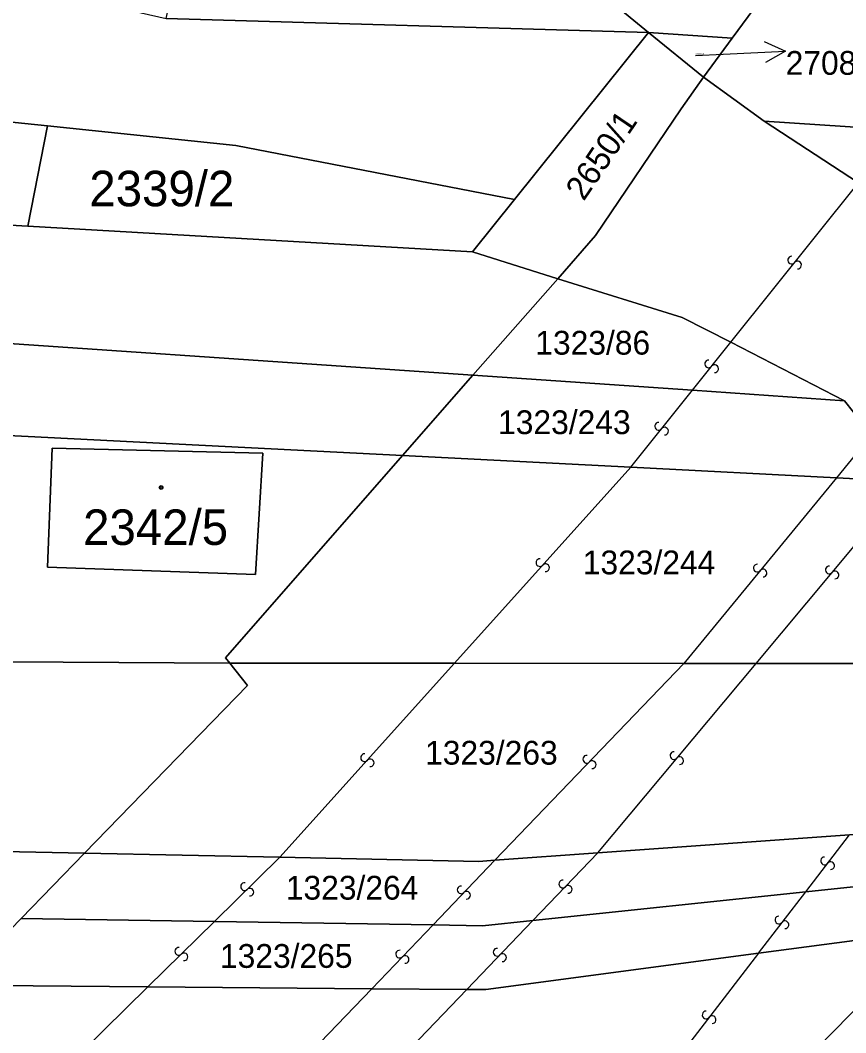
# Model space of a CAD drawing. Extents: x -596024 to -594475, y -1163820 to -1161957.
# Drawn here: x -595780.97 to -595741.38, y -1163112.33 to -1163063.81 of the extents above; entities that cross this region are included whole.
import ezdxf

# ---------------------------------------------------------------- set-up
doc = ezdxf.new("R2010")
doc.units = 0
for name, color, linetype in [('Level 1', 7, 'Continuous'), ('Level 13', 7, 'Continuous'), ('Level 3', 7, 'Continuous'), ('Level 4', 7, 'Continuous'), ('Level 5', 7, 'Continuous'), ('Level 57', 7, 'Continuous'), ('Level 60', 7, 'Continuous')]:
    doc.layers.add(name, color=color, linetype=linetype)

msp = doc.modelspace()

# ---------------------------------------------------------------- linework, layer by layer
at = {"layer": 'Level 1'}
for points in [[(-595779.65, -1163068.86), (-595798.9, -1163066.88), (-595824.16, -1163062.75), (-595839.42, -1163058.15)], [(-595756.75, -1163059.54), (-595750.84, -1163064.39)], [(-595746.83, -1163064.67), (-595743.48, -1163060.13)], [(-595773.96, -1163063.72), (-595750.84, -1163064.39)], [(-595750.84, -1163064.39), (-595757.26, -1163072.39)], [(-595750.84, -1163064.39), (-595746.83, -1163064.67)], [(-595750.84, -1163064.39), (-595748.2, -1163066.53)], [(-595748.2, -1163066.53), (-595746.83, -1163064.67)], [(-595755.19, -1163076.19), (-595753.38, -1163074.12), (-595749.27, -1163068.05), (-595748.2, -1163066.53)], [(-595748.2, -1163066.53), (-595745.29, -1163068.64)], [(-595780.6, -1163073.68), (-595779.65, -1163068.86)], [(-595779.65, -1163068.86), (-595770.62, -1163069.8), (-595757.26, -1163072.39)], [(-595745.29, -1163068.64), (-595740.77, -1163071.6)], [(-595745.29, -1163068.64), (-595738.74, -1163069.07)], [(-595780.6, -1163073.68), (-595817.56, -1163071.57), (-595822.9, -1163070.28)], [(-595759.28, -1163074.91), (-595757.26, -1163072.39)], [(-595780.6, -1163073.68), (-595759.28, -1163074.91)], [(-595759.26, -1163080.82), (-595817.3, -1163076.86), (-595823.71, -1163075.27)], [(-595759.28, -1163074.91), (-595755.19, -1163076.19)], [(-595755.19, -1163076.19), (-595759.26, -1163080.82)], [(-595755.19, -1163076.19), (-595749.22, -1163078.05), (-595746.89, -1163079.24)], [(-595741.44, -1163082.04), (-595746.89, -1163079.24)], [(-595762.63, -1163084.67), (-595816.82, -1163081.91), (-595824.57, -1163080.54)], [(-595759.26, -1163080.82), (-595762.63, -1163084.67)], [(-595759.26, -1163080.82), (-595748.73, -1163081.54)], [(-595748.73, -1163081.54), (-595741.44, -1163082.04)], [(-595740.15, -1163083.68), (-595741.44, -1163082.04)], [(-595779.44, -1163084.32), (-595769.33, -1163084.56), (-595769.69, -1163090.36), (-595779.66, -1163090.01), (-595779.44, -1163084.32)], [(-595762.63, -1163084.67), (-595771.12, -1163094.36), (-595770.92, -1163094.61)], [(-595762.63, -1163084.67), (-595751.68, -1163085.23)], [(-595751.68, -1163085.23), (-595741.83, -1163085.73)], [(-595741.83, -1163085.73), (-595738.38, -1163085.91)], [(-595770.92, -1163094.61), (-595794.91, -1163094.47)], [(-595777.88, -1163103.73), (-595770.07, -1163095.69), (-595770.92, -1163094.61)], [(-595760.14, -1163094.62), (-595770.92, -1163094.61)], [(-595749.14, -1163094.63), (-595760.14, -1163094.62)], [(-595745.68, -1163094.63), (-595749.14, -1163094.63)], [(-595734.88, -1163094.64), (-595745.68, -1163094.63)], [(-595777.88, -1163103.73), (-595815.28, -1163102.95), (-595831.2, -1163101.51)], [(-595753.27, -1163103.71), (-595741.2, -1163102.85)], [(-595780.92, -1163106.86), (-595777.88, -1163103.73)], [(-595777.88, -1163103.73), (-595768.51, -1163103.92)], [(-595768.51, -1163103.92), (-595758.98, -1163104.12), (-595758.2, -1163104.06)], [(-595758.2, -1163104.06), (-595753.27, -1163103.71)], [(-595734.51, -1163104.65), (-595743.3, -1163105.57)], [(-595743.3, -1163105.57), (-595756.38, -1163106.95)], [(-595784.03, -1163110.05), (-595780.92, -1163106.86)], [(-595780.92, -1163106.86), (-595771.65, -1163107)], [(-595771.65, -1163107), (-595761.17, -1163107.16)], [(-595761.17, -1163107.16), (-595758.79, -1163107.2), (-595756.38, -1163106.95)], [(-595745.57, -1163108.52), (-595737.21, -1163107.41)], [(-595745.15, -1163115.51), (-595737.21, -1163107.41)], [(-595745.57, -1163108.52), (-595758.64, -1163110.26), (-595759.55, -1163110.25)], [(-595784.03, -1163110.05), (-595774.84, -1163110.13)], [(-595774.84, -1163110.13), (-595764.11, -1163110.22)], [(-595764.11, -1163110.22), (-595759.55, -1163110.25)]]:
    msp.add_lwpolyline(points, dxfattribs=at)
at = {"layer": 'Level 13'}
for centre, start, end in [((-595743.973, -1163075.303), 88.6764, 320.7744), ((-595743.687, -1163075.536), 268.4619, 141.0519), ((-595747.953, -1163080.273), 88.7129, 320.8109), ((-595747.667, -1163080.506), 268.4985, 141.0885), ((-595750.353, -1163083.264), 88.7319, 320.8299), ((-595750.067, -1163083.496), 268.5174, 141.1074), ((-595756.046, -1163089.795), 85.3552, 317.4532), ((-595755.774, -1163090.044), 265.1407, 137.7307), ((-595745.622, -1163090.063), 87.7604, 320.3504), ((-595745.339, -1163090.298), 267.9748, 140.0728), ((-595742.17, -1163090.15), 87.4381, 319.5361), ((-595741.889, -1163090.389), 267.2237, 139.8137), ((-595764.456, -1163099.145), 85.3855, 317.4835), ((-595753.802, -1163099.222), 83.3047, 315.8947), ((-595749.62, -1163099.05), 87.4804, 319.5784), ((-595749.339, -1163099.289), 267.2659, 139.8559), ((-595764.184, -1163099.394), 265.1711, 137.7611), ((-595753.538, -1163099.479), 263.5191, 135.6171), ((-595742.395, -1163104.096), 89.7025, 321.8005), ((-595742.105, -1163104.323), 269.488, 142.078), ((-595770.208, -1163105.327), 81.8201, 313.9181), ((-595769.952, -1163105.592), 261.6056, 134.1956), ((-595759.822, -1163105.482), 83.3852, 315.9752), ((-595754.952, -1163105.201), 83.5456, 315.6436), ((-595754.688, -1163105.458), 263.3311, 135.9211), ((-595759.558, -1163105.739), 263.5996, 135.6976), ((-595744.585, -1163106.926), 89.7948, 321.8928), ((-595744.295, -1163107.153), 269.5803, 142.1703), ((-595773.368, -1163108.427), 81.8288, 313.9268), ((-595758.102, -1163108.471), 83.5238, 315.6218), ((-595773.112, -1163108.692), 261.6143, 134.2043), ((-595762.772, -1163108.562), 83.304, 315.894), ((-595762.508, -1163108.819), 263.5185, 135.6165), ((-595757.838, -1163108.728), 263.3094, 135.8994), ((-595748.075, -1163111.477), 89.6077, 322.1977), ((-595747.785, -1163111.704), 269.8222, 141.9202)]:
    msp.add_arc(centre, 0.184, start, end, dxfattribs=at)
at = {"layer": 'Level 3'}
for points in [[(-595746.89, -1163079.24), (-595740.77, -1163071.6)], [(-595748.73, -1163081.54), (-595746.89, -1163079.24)], [(-595751.68, -1163085.23), (-595748.73, -1163081.54)], [(-595740.15, -1163083.68), (-595741.83, -1163085.73)], [(-595760.14, -1163094.62), (-595751.68, -1163085.23)], [(-595741.83, -1163085.73), (-595749.14, -1163094.63)], [(-595745.68, -1163094.63), (-595738.38, -1163085.91)], [(-595768.51, -1163103.92), (-595760.14, -1163094.62)], [(-595749.14, -1163094.63), (-595758.2, -1163104.06)], [(-595753.27, -1163103.71), (-595745.68, -1163094.63)], [(-595743.3, -1163105.57), (-595741.2, -1163102.85)], [(-595771.65, -1163107), (-595768.51, -1163103.92)], [(-595756.38, -1163106.95), (-595753.27, -1163103.71)], [(-595758.2, -1163104.06), (-595761.17, -1163107.16)], [(-595745.57, -1163108.52), (-595743.3, -1163105.57)], [(-595774.84, -1163110.13), (-595771.65, -1163107)], [(-595761.17, -1163107.16), (-595764.11, -1163110.22)], [(-595759.55, -1163110.25), (-595756.38, -1163106.95)], [(-595745.57, -1163108.52), (-595750.29, -1163114.66), (-595752.01, -1163116.21)], [(-595782.22, -1163117.37), (-595774.84, -1163110.13)], [(-595764.11, -1163110.22), (-595770.72, -1163117.1)], [(-595766.01, -1163116.99), (-595759.55, -1163110.25)]]:
    msp.add_lwpolyline(points, dxfattribs=at)
at = {"layer": 'Level 5'}
for radius in [0.09, 0.0521]:
    msp.add_circle((-595774.21, -1163086.2), radius, dxfattribs=at)
at = {"layer": 'Level 57'}
for p, q in [((-595748.59, -1163065.49), (-595747.256, -1163065.425)), ((-595747.256, -1163065.425), (-595744.26, -1163065.28))]:
    msp.add_line(p, q, dxfattribs=at)
msp.add_lwpolyline([(-595745.283, -1163064.829), (-595744.26, -1163065.28), (-595745.234, -1163065.828)], dxfattribs=at)
at = {"layer": 'Level 60'}
for points in [[(-595756.75, -1163059.54), (-595750.84, -1163064.39), (-595773.96, -1163063.72), (-595770.91, -1163049.99), (-595770.04, -1163046.08), (-595769.44, -1163043.38), (-595767.99, -1163036.88), (-595764.76, -1163037.03), (-595765.33, -1163056.47), (-595758.86, -1163056.82)], [(-595841.12, -1163065.86), (-595839.42, -1163058.15), (-595824.16, -1163062.75), (-595798.9, -1163066.88), (-595779.65, -1163068.86), (-595780.6, -1163073.68), (-595817.56, -1163071.57), (-595822.9, -1163070.28)], [(-595750.84, -1163064.39), (-595756.75, -1163059.54), (-595743.48, -1163060.13), (-595746.83, -1163064.67)], [(-595755.19, -1163076.19), (-595759.28, -1163074.91), (-595757.26, -1163072.39), (-595750.84, -1163064.39), (-595748.2, -1163066.53), (-595749.27, -1163068.05), (-595753.38, -1163074.12)], [(-595748.2, -1163066.53), (-595750.84, -1163064.39), (-595746.83, -1163064.67)], [(-595748.2, -1163066.53), (-595745.29, -1163068.64), (-595740.77, -1163071.6), (-595739.53, -1163072.41), (-595735, -1163077.41), (-595733.49, -1163079.07), (-595733.06, -1163079.55), (-595730.7, -1163082.19), (-595727.93, -1163085.61), (-595723.18, -1163091.87), (-595722.83, -1163092.35), (-595727.94, -1163097.89), (-595730.64, -1163094.64), (-595732.87, -1163092.03), (-595735.07, -1163089.45), (-595738.38, -1163085.91), (-595740.15, -1163083.68), (-595741.44, -1163082.04), (-595746.89, -1163079.24), (-595749.22, -1163078.05), (-595755.19, -1163076.19), (-595753.38, -1163074.12), (-595749.27, -1163068.05)], [(-595779.65, -1163068.86), (-595770.62, -1163069.8), (-595757.26, -1163072.39), (-595759.28, -1163074.91), (-595780.6, -1163073.68)], [(-595703.87, -1163071.37), (-595706.69, -1163074.49), (-595718.57, -1163073.74), (-595727.72, -1163073.16), (-595731.39, -1163072.93), (-595739.53, -1163072.41), (-595740.77, -1163071.6), (-595745.29, -1163068.64), (-595738.74, -1163069.07), (-595728.81, -1163069.72), (-595725.06, -1163069.97), (-595716.06, -1163070.56)], [(-595759.26, -1163080.82), (-595817.3, -1163076.86), (-595823.71, -1163075.27), (-595822.9, -1163070.28), (-595817.56, -1163071.57), (-595780.6, -1163073.68), (-595759.28, -1163074.91), (-595755.19, -1163076.19)], [(-595762.63, -1163084.67), (-595816.82, -1163081.91), (-595824.57, -1163080.54), (-595823.71, -1163075.27), (-595817.3, -1163076.86), (-595759.26, -1163080.82)], [(-595759.26, -1163080.82), (-595755.19, -1163076.19), (-595749.22, -1163078.05), (-595746.89, -1163079.24), (-595741.44, -1163082.04), (-595748.73, -1163081.54)], [(-595762.63, -1163084.67), (-595759.26, -1163080.82), (-595748.73, -1163081.54), (-595741.44, -1163082.04), (-595740.15, -1163083.68), (-595738.38, -1163085.91), (-595741.83, -1163085.73), (-595751.68, -1163085.23)], [(-595769.33, -1163084.56), (-595779.44, -1163084.32), (-595779.66, -1163090.01), (-595769.69, -1163090.36)], [(-595779.44, -1163084.32), (-595769.33, -1163084.56), (-595769.69, -1163090.36), (-595779.66, -1163090.01)], [(-595771.12, -1163094.36), (-595762.63, -1163084.67), (-595751.68, -1163085.23), (-595741.83, -1163085.73), (-595738.38, -1163085.91), (-595735.07, -1163089.45), (-595732.87, -1163092.03), (-595730.64, -1163094.64), (-595734.88, -1163094.64), (-595745.68, -1163094.63), (-595749.14, -1163094.63), (-595760.14, -1163094.62), (-595770.92, -1163094.61)], [(-595770.07, -1163095.69), (-595777.88, -1163103.73), (-595815.28, -1163102.95), (-595831.2, -1163101.51), (-595830.15, -1163092.76), (-595815.73, -1163094.58), (-595808.11, -1163094.52), (-595794.91, -1163094.47), (-595770.92, -1163094.61)], [(-595777.88, -1163103.73), (-595770.07, -1163095.69), (-595770.92, -1163094.61), (-595760.14, -1163094.62), (-595749.14, -1163094.63), (-595745.68, -1163094.63), (-595734.88, -1163094.64), (-595730.64, -1163094.64), (-595727.94, -1163097.89), (-595728.67, -1163098.68), (-595732.12, -1163102.2), (-595741.2, -1163102.85), (-595753.27, -1163103.71), (-595758.2, -1163104.06), (-595758.98, -1163104.12), (-595768.51, -1163103.92)], [(-595815.28, -1163102.95), (-595777.88, -1163103.73), (-595780.92, -1163106.86), (-595784.03, -1163110.05), (-595814.78, -1163109.8), (-595841.47, -1163108.44), (-595840.88, -1163104.53), (-595840.28, -1163100.69), (-595831.2, -1163101.51)], [(-595780.92, -1163106.86), (-595777.88, -1163103.73), (-595768.51, -1163103.92), (-595758.98, -1163104.12), (-595758.2, -1163104.06), (-595753.27, -1163103.71), (-595741.2, -1163102.85), (-595732.12, -1163102.2), (-595734.51, -1163104.65), (-595743.3, -1163105.57), (-595756.38, -1163106.95), (-595758.79, -1163107.2), (-595761.17, -1163107.16), (-595771.65, -1163107)], [(-595784.03, -1163110.05), (-595780.92, -1163106.86), (-595771.65, -1163107), (-595761.17, -1163107.16), (-595758.79, -1163107.2), (-595756.38, -1163106.95), (-595743.3, -1163105.57), (-595734.51, -1163104.65), (-595737.21, -1163107.41), (-595745.57, -1163108.52), (-595758.64, -1163110.26), (-595759.55, -1163110.25), (-595764.11, -1163110.22), (-595774.84, -1163110.13)], [(-595729.97, -1163106.44), (-595737.81, -1163114.76), (-595745.15, -1163115.51), (-595737.21, -1163107.41)], [(-595786.49, -1163112.58), (-595784.03, -1163110.05), (-595774.84, -1163110.13), (-595764.11, -1163110.22), (-595759.55, -1163110.25), (-595758.64, -1163110.26), (-595745.57, -1163108.52), (-595737.21, -1163107.41), (-595745.15, -1163115.51), (-595752.01, -1163116.21), (-595757.92, -1163116.81), (-595766.01, -1163116.99), (-595770.72, -1163117.1), (-595782.22, -1163117.37), (-595792.85, -1163117.61)]]:
    msp.add_lwpolyline(points, close=True, dxfattribs=at)
for points in [[(-595678.51, -1163041.57), (-595698.09, -1163065.01), (-595703.87, -1163071.37), (-595716.06, -1163070.56), (-595725.06, -1163069.97), (-595728.81, -1163069.72), (-595738.74, -1163069.07), (-595745.29, -1163068.64), (-595748.2, -1163066.53), (-595746.83, -1163064.67), (-595743.48, -1163060.13)], [(-595846.87, -1163047.06), (-595837.67, -1163049.21), (-595828.31, -1163051.33), (-595821.92, -1163052.7), (-595812.73, -1163054.87), (-595794.09, -1163059.15), (-595773.96, -1163063.72), (-595750.84, -1163064.39), (-595757.26, -1163072.39), (-595770.62, -1163069.8), (-595779.65, -1163068.86), (-595798.9, -1163066.88), (-595824.16, -1163062.75), (-595839.42, -1163058.15)], [(-595816.82, -1163081.91), (-595762.63, -1163084.67), (-595771.12, -1163094.36), (-595770.92, -1163094.61), (-595794.91, -1163094.47)]]:
    msp.add_lwpolyline(points, dxfattribs=at)

# ---------------------------------------------------------------- texts
at = {"layer": 'Level 4'}
for s, height, p in [('2708/3', 0.1, (-595748.59, -1163065.49)), ('2339/2', 1.7, (-595777.651, -1163072.72)), ('1323/86', 1.14, (-595756.267, -1163079.83)), ('1323/243', 1.14, (-595758.051, -1163083.64)), ('2342/5', 1.7, (-595777.95, -1163088.95)), ('1323/244', 1.14, (-595753.99, -1163090.36)), ('1323/263', 1.14, (-595761.551, -1163099.48)), ('1323/264', 1.14, (-595768.23, -1163105.95)), ('1323/265', 1.14, (-595771.388, -1163109.22))]:
    msp.add_text(s, height=height, dxfattribs=at).set_placement(p)
msp.add_text('2650/1', height=1.14, rotation=55.898, dxfattribs=at).set_placement((-595753.943, -1163072.51))
at = {"layer": 'Level 57'}
msp.add_text('2708/3', height=1.14, dxfattribs=at).set_placement((-595744.26, -1163066.42))

doc.saveas('drawing.dxf')
